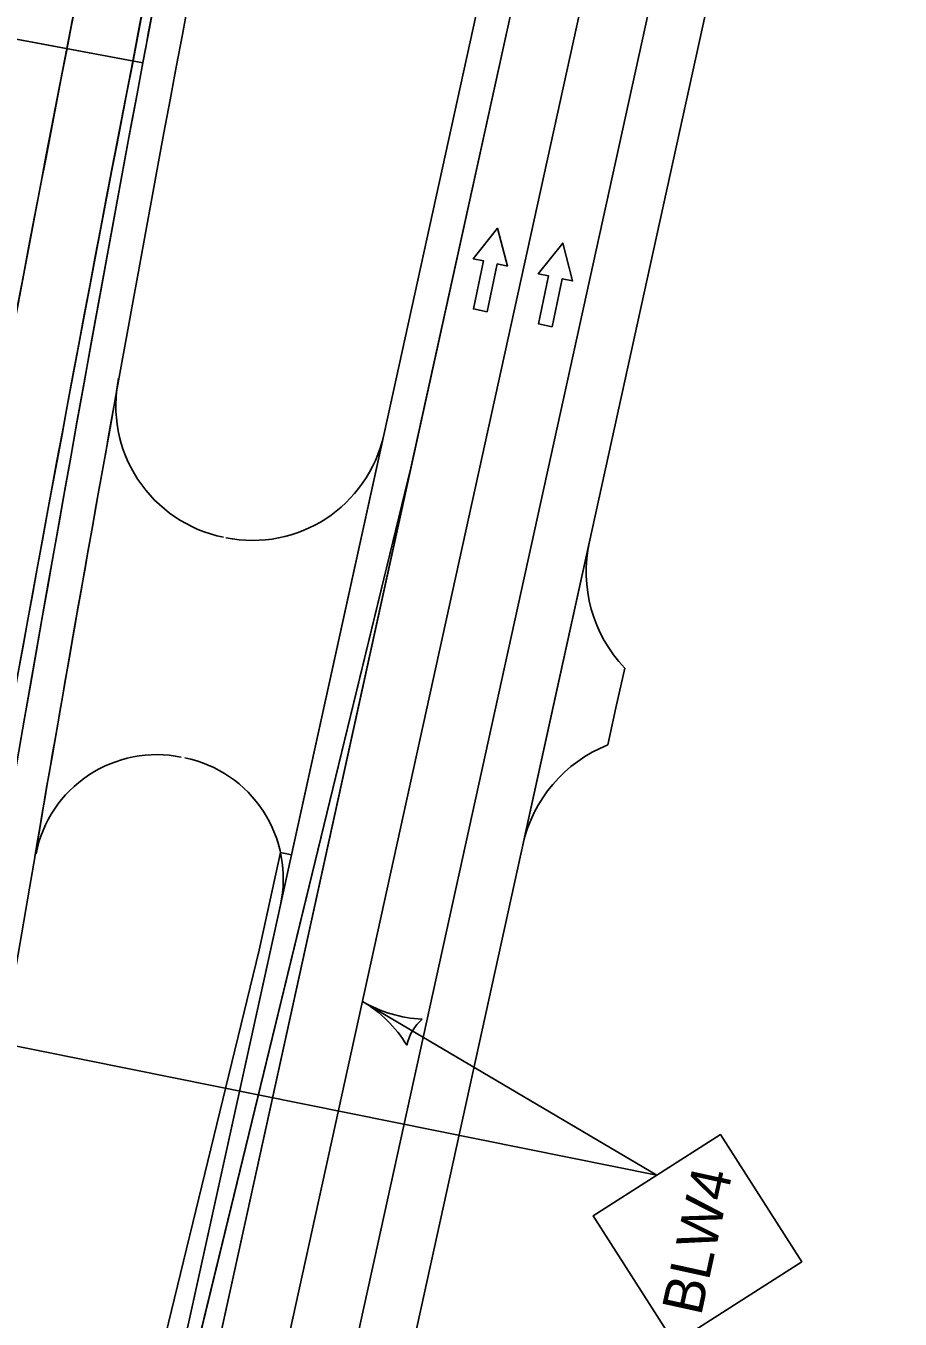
# Model space of a CAD drawing. Extents: x 14107086 to 14122011, y 8637163 to 8671583.
# Drawn here: x 14108060.4 to 14108216.6, y 8640438 to 8640669 of the extents above; entities that cross this region are included whole.
import ezdxf

# ---------------------------------------------------------------- set-up
doc = ezdxf.new("R2010")
doc.units = 0
for name, color, linetype in [('dsn_stg_shd_prev', 7, 'Continuous'), ('dsnPaintExistingEdgeLineLeftYellow', 7, 'Continuous'), ('dsnPaintExistingEdgeLineRightWhite', 7, 'Continuous'), ('dsnPaintPlaceBrokenLaneWhite', 7, 'Continuous'), ('dsnPaintPlaceEdgeLineLeftYellow', 7, 'Continuous'), ('dsnPaintRemoveDoubleCenterLineYellow', 7, 'Continuous'), ('dsnPaintRemoveEdgeLineLeftYellow', 7, 'Continuous'), ('dsnShadingPaved', 7, 'Continuous'), ('dsnStdLabel', 7, 'Continuous'), ('dsnStgShadingPrevPav', 7, 'Continuous'), ('Level 2', 7, 'Continuous'), ('Level 5', 7, 'Continuous')]:
    doc.layers.add(name, color=color, linetype=linetype)

msp = doc.modelspace()

# ---------------------------------------------------------------- linework, layer by layer
at = {"layer": 'dsn_stg_shd_prev'}
for p, q in [((14108081.31, 8640662.43), (14108045.92, 8640669.04)), ((14108057.72, 8640666.84), (14108081.31, 8640662.43))]:
    msp.add_line(p, q, dxfattribs=at)
msp.add_lwpolyline([(14108077.26, 8640401.8), (14108102.07, 8640503.86), (14108105.91, 8640521.35), (14108107.87, 8640520.92), (14108081.5, 8640400.87)], close=True, dxfattribs=at)
for start, end in [(168.328257, 169.413861), (169.413861, 172.222077)]:
    msp.add_arc((14117407.82, 8638919.35), 9488, start, end, dxfattribs=at)
at = {"layer": 'dsnPaintExistingEdgeLineLeftYellow'}
msp.add_lwpolyline([(14108129.2, 8640590.05), (14108700.54, 8643190.87), (14109065.25, 8644884.72)], dxfattribs=at)
msp.add_arc((14117502.5, 8638839.63), 9597.75, 167.26751, 171.3206, dxfattribs=at)
at = {"layer": 'dsnPaintExistingEdgeLineRightWhite'}
msp.add_line((14108110.8, 8640394.44), (14108723.99, 8643185.77), dxfattribs=at)
at = {"layer": 'dsnPaintPlaceBrokenLaneWhite'}
msp.add_lwpolyline([(14109076.98, 8644882.19), (14108712.26, 8643188.32), (14108099.08, 8640397.01)], dxfattribs=at)
msp.add_arc((14117502.5, 8638839.63), 9609.75, 167.26751, 171.3206, dxfattribs=at)
at = {"layer": 'dsnPaintPlaceEdgeLineLeftYellow'}
msp.add_line((14108046.49, 8640249.83), (14108129.2, 8640590.05), dxfattribs=at)
at = {"layer": 'dsnPaintRemoveDoubleCenterLineYellow'}
msp.add_arc((14117394.14, 8638857.08), 9500, 167.610212, 171.325989, dxfattribs=at)
at = {"layer": 'dsnPaintRemoveEdgeLineLeftYellow'}
msp.add_line((14108087.33, 8640399.48), (14108129.2, 8640590.05), dxfattribs=at)
at = {"layer": 'dsnShadingPaved'}
for p, q in [((14108700.55, 8643190.92), (14108087.36, 8640399.59)), ((14108110.8, 8640394.44), (14108723.99, 8643185.77))]:
    msp.add_line(p, q, dxfattribs=at)
msp.add_lwpolyline([(14108083.12, 8640400.52), (14108129.2, 8640590.05), (14108087.36, 8640399.59)], close=True, dxfattribs=at)
for centre, radius, start, end in [((14117394.14, 8638857.08), 9512, 167.610212, 169.436329), ((14117394.14, 8638857.08), 9488, 167.610212, 171.325989), ((14117502.5, 8638839.63), 9621.75, 168.048489, 169.460498)]:
    msp.add_arc(centre, radius, start, end, dxfattribs=at)
at = {"layer": 'dsnStdLabel'}
for q in [(14108120.54, 8640494.73), (14108035.32, 8640491.42)]:
    msp.add_line((14108173.15, 8640463.67), q, dxfattribs=at)
msp.add_lwpolyline([(14108176.33, 8640433.65), (14108199.07, 8640448.2), (14108184.52, 8640470.94), (14108161.78, 8640456.39)], close=True, dxfattribs=at)
for centre, radius, start, end in [((14108108.87, 8640474.97), 22.95, 31.3702, 59.4415), ((14108132.21, 8640514.49), 22.95, 239.4414, 267.5127), ((14108137.11, 8640484.95), 8.86, 131.7072, 167.1757)]:
    msp.add_arc(centre, radius, start, end, dxfattribs=at)
at = {"layer": 'dsnStgShadingPrevPav'}
for p, q in [((14108124.35, 8640595.95), (14108105.9, 8640511.97)), ((14108161.12, 8640576.89), (14108155.11, 8640549.54)), ((14108165.86, 8640547.18), (14108167.42, 8640554.3)), ((14108155.11, 8640549.54), (14108149.21, 8640522.69)), ((14108164.4, 8640540.56), (14108165.86, 8640547.18))]:
    msp.add_line(p, q, dxfattribs=at)
msp.add_lwpolyline([(14108081.5, 8640400.87), (14108123.34, 8640591.33), (14108126.55, 8640605.98), (14108216.67, 8641016.2), (14108268.16, 8641250.61), (14108382.95, 8641773.15), (14108422.02, 8641764.57), (14108309.38, 8641251.8), (14108270.22, 8641073.55), (14108265.93, 8641054.01), (14108255.74, 8641007.62), (14108202.1, 8640763.44), (14108120.56, 8640392.29)], close=True, dxfattribs=at)
for centre, radius, start, end in [((14117407.82, 8638919.35), 9488, 167.610212, 172.222077), ((14117407.82, 8638919.35), 9482, 167.610212, 172.222077), ((14108100.48, 8640601.19), 24, 168.2241, 258.4908), ((14117407.82, 8638919.35), 9482, 169.768725, 170.278029), ((14108100.91, 8640601.1), 24, 258.4908, 347.6102), ((14108185.53, 8640571.53), 25, 167.6114, 223.5657), ((14108173.63, 8640517.32), 25, 111.6547, 167.6089), ((14108083.79, 8640516.82), 22, 78.4908, 168.7454), ((14108084.41, 8640516.69), 22, 347.6102, 78.4908)]:
    msp.add_arc(centre, radius, start, end, dxfattribs=at)
at = {"layer": 'Level 2'}
for points in [[(14108140.38, 8640618.47), (14108142.83, 8640617.95), (14108144.64, 8640626.51), (14108146.47, 8640626.12), (14108144.71, 8640632.88), (14108140.36, 8640627.42), (14108142.19, 8640627.03)], [(14108152.01, 8640615.81), (14108154.45, 8640615.29), (14108156.26, 8640623.85), (14108158.1, 8640623.46), (14108156.34, 8640630.23), (14108151.98, 8640624.76), (14108153.82, 8640624.37)]]:
    msp.add_lwpolyline(points, close=True, dxfattribs=at)
at = {"layer": 'Level 5'}
for points in [[(14108142.19, 8640627.03), (14108140.36, 8640627.42), (14108144.71, 8640632.88), (14108146.47, 8640626.12), (14108144.64, 8640626.51), (14108142.83, 8640617.95), (14108140.38, 8640618.47), (14108142.19, 8640627.03)], [(14108153.82, 8640624.37), (14108151.98, 8640624.76), (14108156.34, 8640630.23), (14108158.1, 8640623.46), (14108156.26, 8640623.85), (14108154.45, 8640615.29), (14108152.01, 8640615.81), (14108153.82, 8640624.37)]]:
    msp.add_lwpolyline(points, dxfattribs=at)

# ---------------------------------------------------------------- texts
at = {"layer": 'dsnStdLabel'}
msp.add_text('BLW4', height=7.2, rotation=77.6078, dxfattribs=at).set_placement((14108181.05, 8640438.39))

doc.saveas('drawing.dxf')
